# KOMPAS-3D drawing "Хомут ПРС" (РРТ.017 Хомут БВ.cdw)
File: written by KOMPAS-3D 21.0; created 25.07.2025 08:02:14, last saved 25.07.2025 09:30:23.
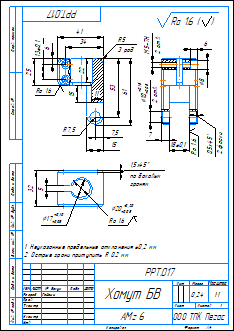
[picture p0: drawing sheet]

Sheet 1: A4, portrait

Document properties: Полное имя файла: ..\Модели КД\РРТ.017 Хомут БВ.m3d; Автор: User; Знак неуказанной шероховатости: 4; Параметр неуказанной шероховатости: Ra 1.6; Масса: 0.239858

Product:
- Part/product: Хомут ПРС
    Масса: 0.239858
    Форматы листов документа: A4
  - Body: Тело 1
      Масса: 0.239922

Title block, sheet 1: Наименование: Хомут БВ; designation: РРТ.017; Материал: АМг 6; Масса: 0,24; Количество листов документа: 1; organisation: ООО ТПК Пегас; Форматы листов документа: A4; stored path: C:\Users\User\Desktop\Ручной ротатор КД\Чертежи\РРТ.017 Хомут БВ.cdw; Разработал: Гайсин

Views: Вид 1, Местный разрез 1, Спереди, Проекционный вид 2, Местный разрез 2, Проекционный вид 3
Referenced files in C:\Users\User\Desktop\Ручной ротатор КД\Модели КД\: РРТ.017 Хомут БВ.m3d
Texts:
  Ra 1.6
  Хомут ПРС
  по боковым
  граням
  Ra 1.6 ( )
Dimensions and other numbers on the sheet: 41; 25; 53; 61; 34; 13±0,1; 6; 22; 11; 15; 7,5; 5; 3 рад; 7; 8; -7Н; 2 отв; 18±0,1; 10; 0,5; 2 фаски; 32; 20; 17; 1,5; 2; 1:1; 1; 0,24

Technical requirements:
  Неуказанные предельные отклонения  0,2 мм
  Острые грани притупить R 0.2 мм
